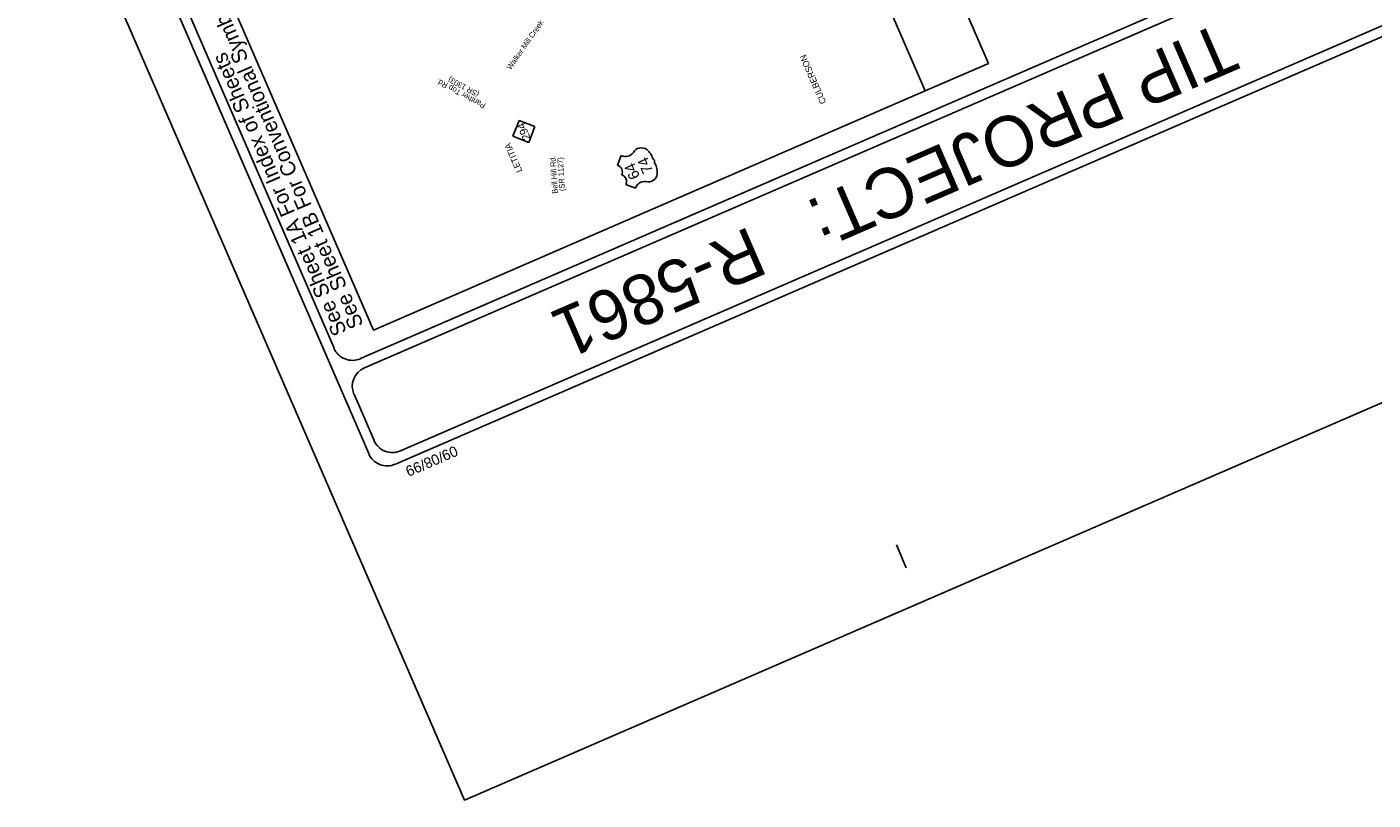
# Model space of a CAD drawing. Extents: x 442728 to 492797, y 479541 to 511293.
# Drawn here: x 471963 to 482000, y 481554 to 487323 of the extents above; entities that cross this region are included whole.
import ezdxf

# ---------------------------------------------------------------- set-up
doc = ezdxf.new("R2010")
doc.units = 0
for name, color, linetype in [('Default', 7, 'Continuous'), ('Old_Level_1', 7, 'Continuous'), ('Old_Level_22', 7, 'Continuous'), ('Prop DSN Text', 7, 'Continuous'), ('Prop Grid Mask', 7, 'Continuous'), ('Prop PHM Text', 7, 'Continuous'), ('Prop PHM White Label Box', 7, 'Continuous'), ('Sheet Plot Border Outside CELL', 7, 'Continuous'), ('Sheet Title CELL', 7, 'Continuous')]:
    doc.layers.add(name, color=color, linetype=linetype)

msp = doc.modelspace()

# ---------------------------------------------------------------- linework, layer by layer
at = {"layer": 'Old_Level_1'}
for points in [[(479132, 487049), (476717, 492620), (476245, 492415), (478661, 486845)], [(478661, 486845), (476245, 492415), (472131, 490631), (474547, 485061)], [(478661, 486845), (476245, 492415), (472131, 490631), (474547, 485061)], [(478661, 486845), (476245, 492415), (472131, 490631), (474547, 485061)], [(478661, 486845), (476245, 492415), (472131, 490631), (474547, 485061)]]:
    msp.add_lwpolyline(points, close=True, dxfattribs=at)
at = {"layer": 'Prop Grid Mask'}
for p, q in [((476367, 486291), (476395, 486363)), ((476501, 486119), (476429, 486148)), ((476579, 486169), (476579, 486169))]:
    msp.add_line(p, q, dxfattribs=at)
for centre, radius, start, end in [((476427, 486426), 70.6, 243.0256, 325.3656), ((476544, 486354), 67.1, 52.9078, 151.9677), ((476498, 486300), 138, 17.6313, 51.1919), ((476649, 486346), 19.6, 189.9394, 254.6384), ((476661, 486317), 19.6, 150.0064, 217.0678), ((476352, 486242), 51.2, 332.648, 72.4987), ((476596, 486234), 67.1, 255.049, 354.1035), ((476525, 486237), 138, 355.8194, 29.3915), ((476383, 486170), 51.2, 334.589, 73.4331), ((476568, 486099), 70.6, 81.6457, 163.5445)]:
    msp.add_arc(centre, radius, start, end, dxfattribs=at)
at = {"layer": 'Prop PHM White Label Box'}
for p, q in [((475634, 486625), (475586, 486507)), ((475751, 486579), (475634, 486625)), ((475706, 486460), (475751, 486579)), ((475586, 486507), (475706, 486460))]:
    msp.add_line(p, q, dxfattribs=at)
at = {"layer": 'Sheet Plot Border Outside CELL'}
msp.add_lwpolyline([(465175, 504729), (475225, 481554), (490363, 488118), (480314, 511293)], close=True, dxfattribs=at)
at = {"layer": 'Sheet Title CELL'}
for p, q in [((488517, 490866), (474480, 484779)), ((485942, 489831), (474450, 484848)), ((478520, 483286), (478446, 483458)), ((478520, 483286), (478446, 483458))]:
    msp.add_line(p, q, dxfattribs=at)
for points in [[(465681, 504507), (474512, 484139)], [(465779, 504468), (474253, 484926)], [(474749, 484160), (488786, 490246)], [(474710, 484061), (488885, 490208)], [(474710, 484061), (488885, 490208)], [(474402, 484582), (474551, 484238)]]:
    msp.add_lwpolyline(points, dxfattribs=at)
for centre, start, end in [((474390, 484985), 203.4424, 293.4424), ((474539, 484641), 113.4424, 203.4424), ((474688, 484297), 203.4424, 293.4424), ((474649, 484198), 203.4424, 293.4424)]:
    msp.add_arc(centre, 150, start, end, dxfattribs=at)

# ---------------------------------------------------------------- texts
at = {"layer": 'Default'}
msp.add_text('Walker Mill Creek', height=41.38, rotation=55.135, dxfattribs=at).set_placement((475571, 487000))
at = {"layer": 'Old_Level_22'}
for s, height, rotation, p in [('CULBERSON', 47.3, 113.4424, (477924, 486760)), ('Panther Top Rd.', 41.38, 151.7198, (475387, 486748)), ('(SR 1303)', 41.4, 151.7198, (475340, 486834)), ('LETITIA', 47.3, 113.4424, (475658, 486249)), ('Bell Hill Rd.', 41.38, 93.7294, (475922, 486080)), ('(SR 1127)', 41.4, 93.7294, (475975, 486100))]:
    msp.add_text(s, height=height, rotation=rotation, dxfattribs=at).set_placement(p)
at = {"layer": 'Prop DSN Text'}
for s, p in [('74', (476634, 486249)), ('64', (476536, 486206))]:
    msp.add_text(s, height=81.2, rotation=113.5056, dxfattribs=at).set_placement(p)
at = {"layer": 'Prop PHM Text'}
msp.add_text('294', height=59.7, rotation=113.4424, dxfattribs=at).set_placement((475721, 486493))
at = {"layer": 'Sheet Title CELL'}
for s, height, rotation, p in [('See Sheet 1B For Conventional Symbols', 112.5, 113.4424, (474475, 485101)), ('TIP PROJECT:', 375, 203.4424, (480872, 487364)), ('See Sheet 1A For Index of Sheets', 112.5, 113.4424, (474351, 485048)), ('R-5861', 375, 203.4424, (477355, 485839)), ('09/08/99', 78.8, 203.4424, (475154, 484201))]:
    msp.add_text(s, height=height, rotation=rotation, dxfattribs=at).set_placement(p)

doc.saveas('drawing.dxf')
